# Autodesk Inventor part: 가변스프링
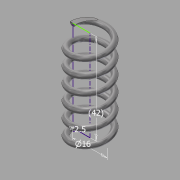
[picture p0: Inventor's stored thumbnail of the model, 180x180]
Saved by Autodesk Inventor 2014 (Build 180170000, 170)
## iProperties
Created: 2015-07
Part Number: 가변스프링
Material: 강철, 탄소
Document SubType Name: Modeling
Designer: study
Density: 7.87 g/cm^3
Appearance: 반연마
Mass: 11.5077 g
Surface Area: 23.7555 cm^2
Volume: 1.46223 cm^3
Author: study
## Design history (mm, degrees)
sketch "스케치2"
  geometry: L1 (0, 0)-(0, 42); L2 (0, 42)-(8, 42); L3 (8, 42)-(8, 0); L4 (8, 0)-(0, 0); C1 r 1.25 at (8, 0)
  constraints: 8 end point, 2 parallel, 1 centre point, 1 coincident, 1 perpendicular, 1 vertical
  dimensions: "d1" = 16 diameter of L3 L1; "d2" = 42 distance of L1.start L1.end (derived); "d3" = 2.5 diameter of C1
feature "코일1" pitch "d4" = 10; turns "d6" = 6; dims "d5" = 42 (= d2), "d7" = 0, angle "d8" = 90 deg, angle "d9" = 90 deg, "d10" = 0, "d11" = 0
node "작업 평면1"
sketch "스케치3"
  geometry: L1 (6.75, 0)-(9.25, 0) reference; 1 further point
  constraints: 1 horizontal alignment
extrude "돌출1" cut sketch "스케치3" stored distance "d13" = 10; taper "d14" = 0 deg
node "작업 평면2"
sketch "스케치4"
  geometry: L1 (-1.25, 0)-(1.25, 0) reference; 1 further point
  constraints: 1 horizontal alignment
extrude "돌출2" cut sketch "스케치4" stored distance "d16" = 10; taper "d17" = 0 deg
node "솔리드1"
node "절단 모서리 투영1"
node "절단 모서리 투영2"
other parameters: "d12" = 90 deg, "d15" = 90 deg
